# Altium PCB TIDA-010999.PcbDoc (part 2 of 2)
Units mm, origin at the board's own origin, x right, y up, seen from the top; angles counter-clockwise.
Board outline 95 x 90.17 mm, 4 copper layers (Top Layer 1, Top Layer, Bottom Layer, Bottom Layer 1), stack 1.926 mm thick; 90 components, 100 nets, 358 pads, 545 vias.
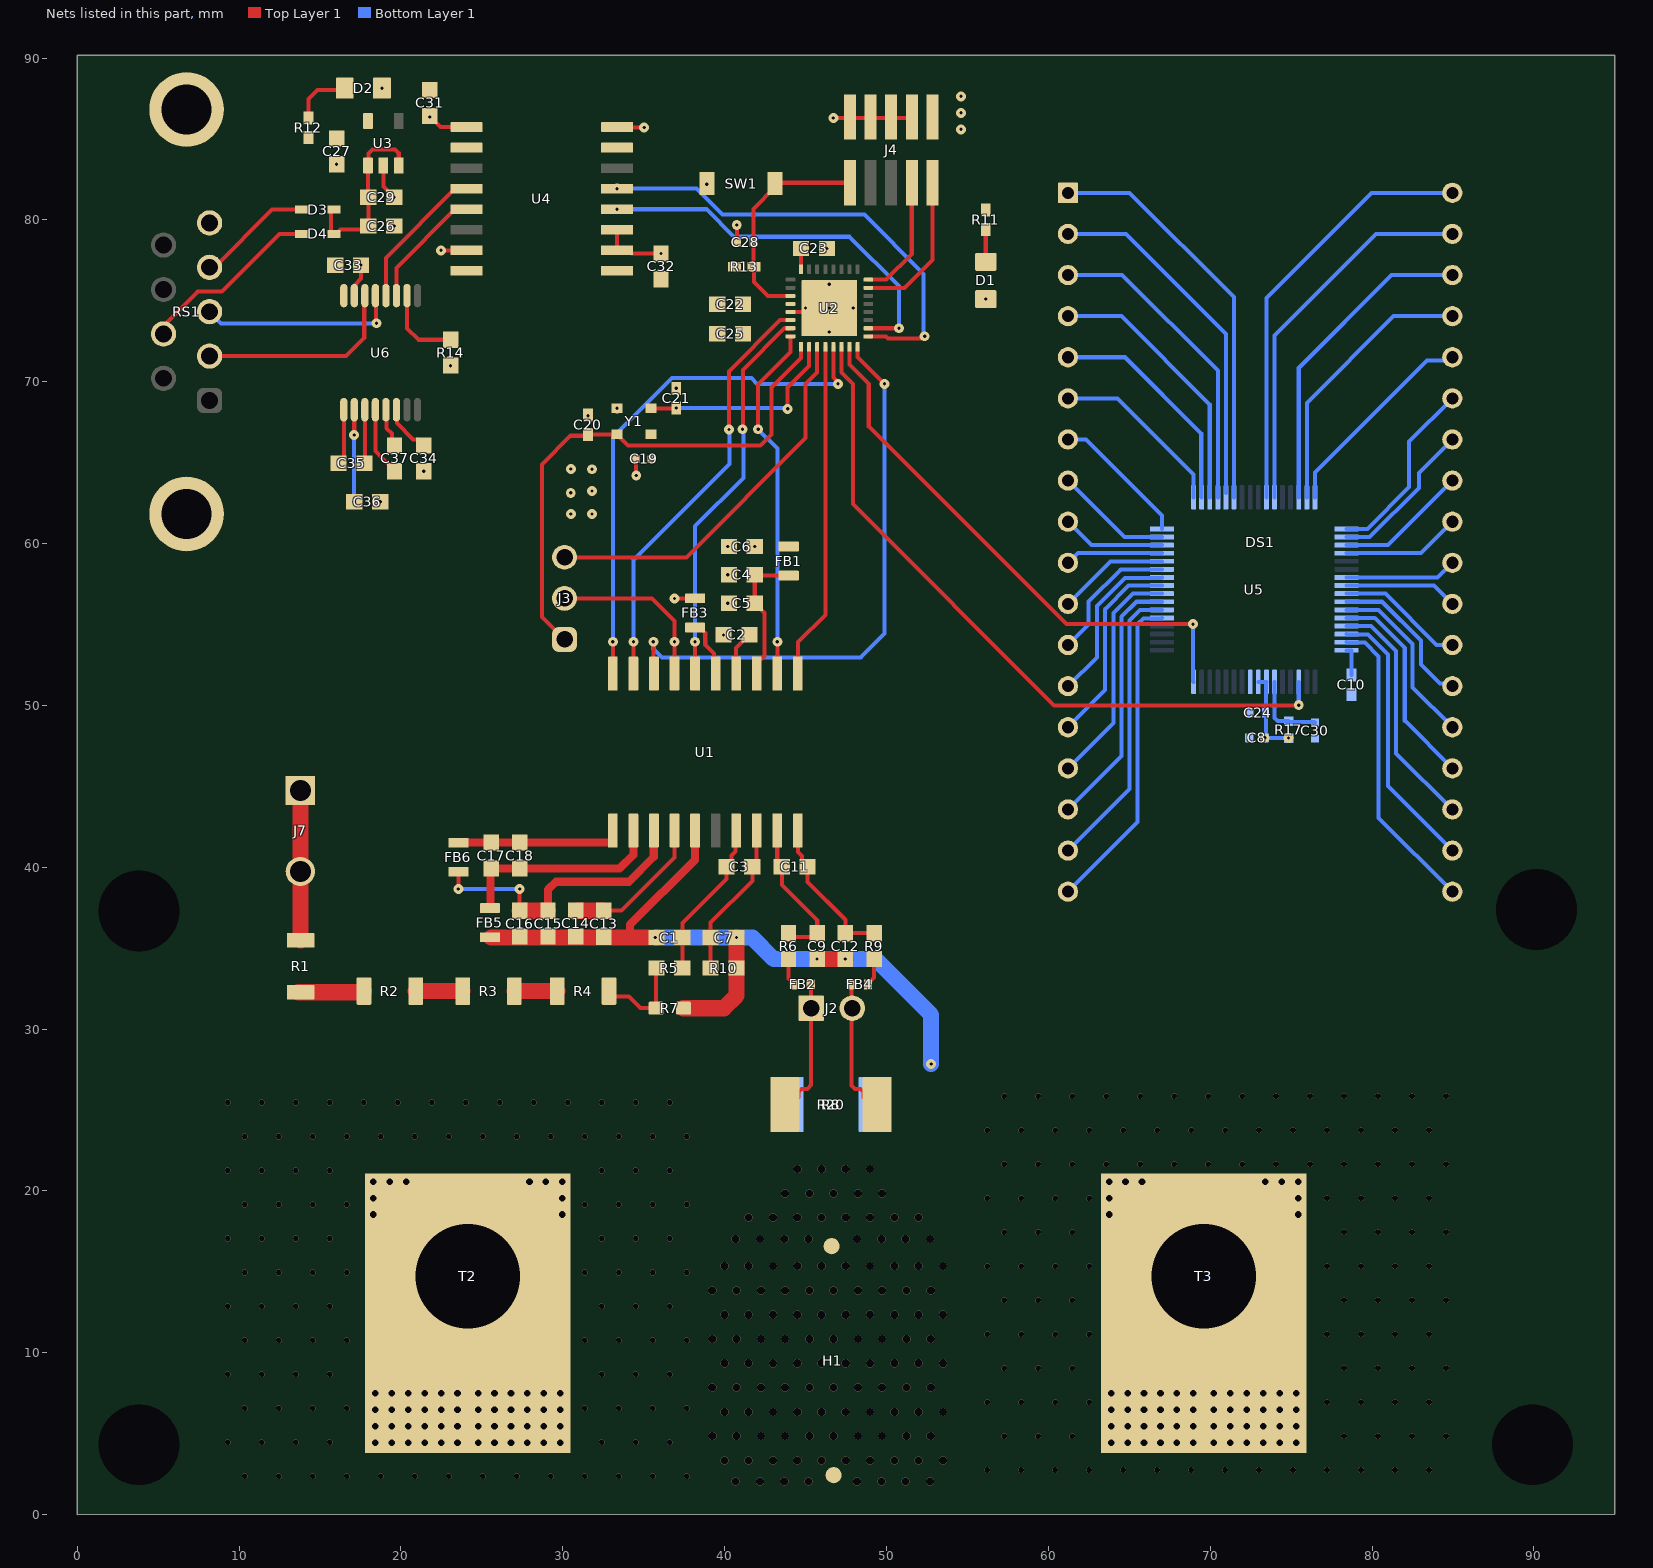
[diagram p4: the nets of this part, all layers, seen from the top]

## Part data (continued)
U4: library part CMP-0094636-1, Digikey Part Number=296-ISO6731DWRCT-ND, Manufacturer="Texas Instruments", Max Supply Voltage=5.5V, Min Supply Voltage=1.71V, Mouser Part Number=595-ISO6731DWR, Operating Temperature Range="-40°C to +125°C"
U5: library part CMP-0120470-1, "Automotive Mixed-Signal Microcontroller, LQFP64", Frequency_Fixed=32MHz, Manufacturer="Texas Instruments", Max Supply Voltage=3.6V, Min Supply Voltage=1.62V, Operating Temperature Range="-40°C to +125°C"
U6: library part CMP-0044119-1, "3-V to 5.5-V Multichannel RS-232 Line Driver / Receiver with ±15-kV IEC ESD Protection, -40 to 85 degC, 16-Pin SSOP (DB), Green (RoHS & no Sb/Br)", Drivers Per Package=2, Supply Voltage(s)(V)="3.3 or 5.0"
Y1: library part CMP-0094615-2, "Crystal replacement: Ultra-low Power LVCMOS Oscillator 4-pin, VSON 3.2 x 2.5 x 0.9mm", Frequency Stability=20ppm, Frequency_Fixed=50MHz, Load Capacitance=15pF, Manufacturer="Texas Instruments", Max Supply Current=4mA, Max Supply Voltage=3.465V, Min Supply Voltage=2.375V, Operating Temperature Range="to +135°C", Part Number=CDC6CE05000CDLE

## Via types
v1: diameter 0.35, hole 0.35, Top Layer 1 to Bottom Layer 1, 225 vias
v2: diameter 0.5, hole 0.5, Top Layer 1 to Bottom Layer 1, 123 vias
v3: diameter 0.813, hole 0.406, Top Layer 1 to Bottom Layer 1, 116 vias
v4: diameter 0.61, hole 0.203, Top Layer 1 to Bottom Layer 1, tented both sides, 76 vias
v5: diameter 0.5, hole 0.2, Top Layer 1 to Bottom Layer 1, 5 vias

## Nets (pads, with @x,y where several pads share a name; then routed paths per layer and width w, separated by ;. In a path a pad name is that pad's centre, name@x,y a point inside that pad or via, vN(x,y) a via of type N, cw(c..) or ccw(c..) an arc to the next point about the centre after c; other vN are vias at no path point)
ADC_C\S\: U1.19 U2.6 | length 26.3
  Top Layer 1 w0.25: U1.19@34.362,51.967 v4(34.362,53.937) ; v4(40.272,67.053) 40.264,67.06 40.264,70.643 43.426,73.805 U2.6@44.068,73.805
  Bottom Layer 1 w0.25: v4(34.362,53.937) 34.362,58.977 40.307,64.922 40.307,67.018 v4(40.272,67.053)
ADC_CLK_IN: J3.2 U1.17 | length 10.6
  Top Layer 1 w0.25: J3.2@30.105,56.612 35.499,56.612 36.902,55.21 v4(36.902,53.937) U1.17@36.902,51.967
ADC_D\R\D\Y\: U1.16 U2.7 | length 24
  Top Layer 1 w0.25: U1.16@38.172,51.967 v4(38.172,53.937) ; v4(41.105,67.06) 41.138,67.093 41.138,70.73 43.713,73.305 U2.7@44.068,73.305
  Bottom Layer 1 w0.25: v4(38.172,53.937) 38.172,61.07 41.153,64.051 41.153,67.012 v4(41.105,67.06)
ADC_DIN_MSP_DOUT: U1.20 U2.13 | length 32.6
  Top Layer 1 w0.25: U1.20@33.092,51.967 v4(33.092,53.937) ; U2.13@46.718,72.155 46.718,70.257 47.007,69.968 v4(47.007,69.87)
  Bottom Layer 1 w0.25: v4(33.092,53.937) 33.092,66.575 36.745,70.228 41.648,70.228 42.006,69.87 v4(47.007,69.87)
ADC_DOUT_MSP_DIN: U1.12 U2.8 | length 22.2
  Top Layer 1 w0.25: v4(42.07,67.06) 42.07,69.836 44.068,71.834 U2.8@44.068,72.805 ; U1.12@43.252,51.967 43.253,51.968 43.253,53.935 v4(43.255,53.937)
  Bottom Layer 1 w0.25: v4(42.07,67.06) 43.255,65.875 v4(43.255,53.937)
ADC_SYNC_RESET: U1.11 U2.12 | length 20.9
  Top Layer 1 w0.25: U1.11@44.522,51.967 44.522,53.905 46.218,55.601 U2.12@46.218,72.155
Bus_In: FB2.2 J2.1 R8.2 R20.2 T2.1 | length 8.7
  Top Layer 1 w0.254: R8.2@43.448,25.852 R8.2@44.486,25.852 ; R8.2@44.571,25.768 44.571,26.127 44.747,26.304 45.107,26.304 45.343,26.54 45.344,29.923 FB2.2@45.345,32.658 ; FB2.2@45.29,32.603 FB2.2@45.442,32.755
  other v1: 10.357,2.364 12.457,2.364 14.557,2.364 16.657,2.364 18.757,2.364 20.857,2.364 22.957,2.364 25.057,2.364 27.157,2.364 29.257,2.364 31.357,2.364 33.457,2.364 35.557,2.364 37.657,2.364 9.307,4.464 11.407,4.464 13.507,4.464 15.607,4.464 32.407,4.464 34.507,4.464 36.607,4.464 10.357,6.564 12.457,6.564 14.557,6.564 16.657,6.564 31.357,6.564 33.457,6.564 35.557,6.564 37.657,6.564 9.307,8.664 11.407,8.664 13.507,8.664 15.607,8.664 32.407,8.664 34.507,8.664 36.607,8.664 10.357,10.764 12.457,10.764 14.557,10.764 16.657,10.764 31.357,10.764 33.457,10.764 35.557,10.764 37.657,10.764 9.307,12.864 11.407,12.864 13.507,12.864 15.607,12.864 32.407,12.864 34.507,12.864 36.607,12.864 10.357,14.964 12.457,14.964 14.557,14.964 16.657,14.964 31.357,14.964 33.457,14.964 35.557,14.964 37.657,14.964 9.307,17.064 11.407,17.064 13.507,17.064 15.607,17.064 32.407,17.064 34.507,17.064 36.607,17.064 10.357,19.164 12.457,19.164 14.557,19.164 16.657,19.164 31.357,19.164 33.457,19.164 35.557,19.164 37.657,19.164 9.307,21.264 11.407,21.264 13.507,21.264 15.607,21.264 32.407,21.264 34.507,21.264 36.607,21.264 10.357,23.364 12.457,23.364 14.557,23.364 16.657,23.364 18.757,23.364 20.857,23.364 22.957,23.364 25.057,23.364 27.157,23.364 29.257,23.364 31.357,23.364 33.457,23.364 35.557,23.364 37.657,23.364 9.307,25.464 11.407,25.464 13.507,25.464 15.607,25.464 17.707,25.464 19.807,25.464 21.907,25.464 24.007,25.464 26.107,25.464 28.207,25.464 30.307,25.464 32.407,25.464 34.507,25.464 36.607,25.464
  other v3: 18.415,4.445 19.431,4.445 20.447,4.445 21.463,4.445 22.479,4.445 23.495,4.445 24.765,4.445 25.781,4.445 26.797,4.445 27.813,4.445 28.829,4.445 29.845,4.445 18.415,5.461 19.431,5.461 20.447,5.461 21.463,5.461 22.479,5.461 23.495,5.461 24.765,5.461 25.781,5.461 26.797,5.461 27.813,5.461 28.829,5.461 29.845,5.461 18.415,6.477 19.431,6.477 20.447,6.477 21.463,6.477 22.479,6.477 23.495,6.477 24.765,6.477 25.781,6.477 26.797,6.477 27.813,6.477 28.829,6.477 29.845,6.477 18.415,7.493 19.431,7.493 20.447,7.493 21.463,7.493 22.479,7.493 23.495,7.493 24.765,7.493 25.781,7.493 26.797,7.493 27.813,7.493 28.829,7.493 29.845,7.493 18.288,18.542 29.972,18.542 18.288,19.558 29.972,19.558 18.288,20.574 19.304,20.574 20.32,20.574 27.94,20.574 28.956,20.574 29.972,20.574
DCDC_HGND: C17.2 C18.1 FB5.1 U1.2 | length 13.1
  Top Layer 1 w0.5: FB5.1@25.495,37.477 25.534,37.516 25.534,39.88 C17.2@25.573,39.919 C18.1@27.335,39.919 33.512,39.919 34.362,40.769 U1.2@34.362,42.267
DCDC_OUT: C17.1 C18.2 FB6.1 U1.1 | length 10.3
  Top Layer 1 w0.5: FB6.1@23.547,41.515 23.552,41.519 C17.1@25.573,41.519 C18.2@27.335,41.519 33.042,41.519 33.092,41.569 U1.1@33.092,42.267
GND: C2.2 C4.2 C5.1 C6.1 C8.1 C10.1 C19.1 C20.2 C21.1 C22.1 C23.1 C24.1 C25.1 C28.1 C30.1 C32.2 D1.2 FB3.2 J4.3 J4.5 J4.7 J4.9 SW1.1 U2.5 U2.33 U4.2 U4.3 U4.8 U5.41 Y1.2 | length 15.1
  Top Layer 1 w0.25: U4.3@33.352,79.388 U4.2@33.352,78.118 34.052,78.118 34.243,77.927 v4(36.068,77.927) ; U4.8@33.352,85.738 33.369,85.721 35.01,85.721 v4(35.027,85.705) ; C19.1@34.49,65.226 34.516,65.201 34.516,64.237 v4(34.541,64.211) ; v4@36.902,56.612 FB3.2@38.171,56.612 ; v4(40.745,79.689) 40.758,79.676 40.758,78.625 C28.1@40.77,78.613 ; U2.5@44.068,74.305 44.868,74.305 44.993,74.43 v5(44.993,74.555) ; v4(46.718,86.298) 51.497,86.298 J4.3@51.562,86.363
  other v4: 39.932,54.356 40.184,56.31 36.902,56.611 40.184,58.082 40.184,59.817 31.554,67.903 33.35,68.353 37.006,69.598 39.538,72.969 39.538,74.791 56.134,75.105 46.328,78.232 38.892,82.193
  other v5: 46.468,73.08 46.468,74.555 47.943,74.555 46.468,76.03
GND_ISO_RS: C26.2 C27.2 C29.2 C31.2 C33.1 C34.1 C36.1 D2.2 R14.1 RS1.5 RS1.10 RS1.11 U3.2 U4.9 U4.15 U6.15 | length 8.4
  Top Layer 1 w0.25: U6.15@17.119,75.32 17.158,75.358 17.158,75.986 17.536,76.365 v4(17.536,77.206) ; U3.2@18.912,83.361 18.912,82.049 v4(19.556,81.405) C29.2@19.581,81.405 ; v4(21.784,86.353) 21.834,86.353 22.449,85.738 U4.9@24.052,85.738 ; v4(22.477,78.118) U4.15@24.052,78.118
  other v4: 18.718,62.576 21.403,64.466 23.065,70.995 19.581,79.621 16.022,83.436 18.822,88.138
H_GND: C1.2 C7.1 C9.2 C12.1 C13.2 C14.2 C15.2 C16.2 FB4.2 FB5.2 J2.2 R7.1 R8.1 R10.1 R20.1 T3.1 U1.5 | length 58.1
  Top Layer 1 w0.254: FB4.2@47.844,32.749 47.844,29.923 47.844,26.507 48.042,26.308 48.401,26.308 48.581,26.129 R8.1@48.581,25.77 ; R8.1@48.659,25.848 R8.1@49.795,25.848
  Top Layer 1 w0.5: 34.158,35.657 34.158,36.453 38.16,40.455 U1.5@38.16,42.255
  Top Layer 1 w1: FB5.2@25.577,35.657 29.085,35.657 34.158,35.657 v4(35.707,35.657) C1.2@35.782,35.657 ; R7.1@37.457,31.289 39.955,31.289 40.732,32.066 R10.1@40.732,33.771 v4(40.732,35.657) ; v4(45.71,34.324) v4(47.449,34.324)
  Bottom Layer 1 w1: v4(35.707,35.657) 41.713,35.657 43.045,34.324 v4(45.71,34.324) v4(47.449,34.324) 48.366,34.324 48.379,34.338 49.297,34.338 52.757,30.877 v4(52.757,27.841)
  other v1: 56.221,2.752 58.321,2.752 60.421,2.752 62.521,2.752 64.621,2.752 66.721,2.752 68.821,2.752 70.921,2.752 73.021,2.752 75.121,2.752 77.221,2.752 79.321,2.752 81.421,2.752 83.521,2.752 57.271,4.852 59.371,4.852 61.471,4.852 78.271,4.852 80.371,4.852 82.471,4.852 84.571,4.852 56.221,6.952 58.321,6.952 60.421,6.952 62.521,6.952 77.221,6.952 79.321,6.952 81.421,6.952 83.521,6.952 57.271,9.052 59.371,9.052 61.471,9.052 78.271,9.052 80.371,9.052 82.471,9.052 84.571,9.052 56.221,11.152 58.321,11.152 60.421,11.152 62.521,11.152 77.221,11.152 79.321,11.152 81.421,11.152 83.521,11.152 57.271,13.252 59.371,13.252 61.471,13.252 78.271,13.252 80.371,13.252 82.471,13.252 84.571,13.252 56.221,15.352 58.321,15.352 60.421,15.352 62.521,15.352 77.221,15.352 79.321,15.352 81.421,15.352 83.521,15.352 57.271,17.452 59.371,17.452 61.471,17.452 78.271,17.452 80.371,17.452 82.471,17.452 84.571,17.452 56.221,19.552 58.321,19.552 60.421,19.552 62.521,19.552 77.221,19.552 79.321,19.552 81.421,19.552 83.521,19.552 57.271,21.652 59.371,21.652 61.471,21.652 63.571,21.652 65.671,21.652 67.771,21.652 69.871,21.652 71.971,21.652 74.071,21.652 76.171,21.652 78.271,21.652 80.371,21.652 82.471,21.652 84.571,21.652 56.221,23.752 58.321,23.752 60.421,23.752 62.521,23.752 64.621,23.752 66.721,23.752 68.821,23.752 70.921,23.752 73.021,23.752 75.121,23.752 77.221,23.752 79.321,23.752 81.421,23.752 83.521,23.752 57.271,25.852 59.371,25.852 61.471,25.852 63.571,25.852 65.671,25.852 67.771,25.852 69.871,25.852 71.971,25.852 74.071,25.852 76.171,25.852 78.271,25.852 80.371,25.852 82.471,25.852 84.571,25.852
  other v3: 63.881,4.445 64.897,4.445 65.913,4.445 66.929,4.445 67.945,4.445 68.961,4.445 70.231,4.445 71.247,4.445 72.263,4.445 73.279,4.445 74.295,4.445 75.311,4.445 63.881,5.461 64.897,5.461 65.913,5.461 66.929,5.461 67.945,5.461 68.961,5.461 70.231,5.461 71.247,5.461 72.263,5.461 73.279,5.461 74.295,5.461 75.311,5.461 63.881,6.477 64.897,6.477 65.913,6.477 66.929,6.477 67.945,6.477 68.961,6.477 70.231,6.477 71.247,6.477 72.263,6.477 73.279,6.477 74.295,6.477 75.311,6.477 63.881,7.493 64.897,7.493 65.913,7.493 66.929,7.493 67.945,7.493 68.961,7.493 70.231,7.493 71.247,7.493 72.263,7.493 73.279,7.493 74.295,7.493 75.311,7.493 63.754,18.542 75.438,18.542 63.754,19.558 75.438,19.558 63.754,20.574 64.77,20.574 65.786,20.574 73.406,20.574 74.422,20.574 75.438,20.574
HEAT: H1.1 H1.2
  other v2: 40.682,2.036 42.182,2.036 43.682,2.036 45.182,2.036 48.182,2.036 49.682,2.036 51.182,2.036 52.682,2.036 39.984,3.351 41.484,3.351 42.984,3.351 44.484,3.351 45.984,3.351 47.484,3.351 48.984,3.351 50.484,3.351 51.984,3.351 53.484,3.351 39.234,4.851 40.734,4.851 42.234,4.851 43.734,4.851 45.234,4.851 46.734,4.851 48.234,4.851 49.734,4.851 51.234,4.851 52.734,4.851 39.984,6.351 41.484,6.351 42.984,6.351 44.484,6.351 45.984,6.351 47.484,6.351 48.984,6.351 50.484,6.351 51.984,6.351 53.484,6.351 39.234,7.851 40.734,7.851 42.234,7.851 43.734,7.851 45.234,7.851 46.734,7.851 48.234,7.851 49.734,7.851 51.234,7.851 52.734,7.851 39.984,9.351 41.484,9.351 42.984,9.351 44.484,9.351 45.984,9.351 47.484,9.351 48.984,9.351 50.484,9.351 51.984,9.351 53.484,9.351 39.234,10.851 40.734,10.851 42.234,10.851 43.734,10.851 45.234,10.851 46.734,10.851 48.234,10.851 49.734,10.851 51.234,10.851 52.734,10.851 39.984,12.351 41.484,12.351 42.984,12.351 44.484,12.351 45.984,12.351 47.484,12.351 48.984,12.351 50.484,12.351 51.984,12.351 53.484,12.351 39.234,13.851 40.734,13.851 42.234,13.851 43.734,13.851 45.234,13.851 46.734,13.851 48.234,13.851 49.734,13.851 51.234,13.851 52.734,13.851 39.984,15.351 41.484,15.351 42.984,15.351 44.484,15.351 45.984,15.351 47.484,15.351 48.984,15.351 50.484,15.351 51.984,15.351 53.484,15.351 40.682,17.036 42.182,17.036 43.682,17.036 45.182,17.036 48.182,17.036 49.682,17.036 51.182,17.036 52.682,17.036 41.484,18.351 42.984,18.351 44.484,18.351 45.984,18.351 47.484,18.351 48.984,18.351 50.484,18.351 51.984,18.351 43.734,19.851 45.234,19.851 46.734,19.851 48.234,19.851 49.734,19.851 44.484,21.351 45.984,21.351 47.484,21.351 48.984,21.351
HFXIN: C20.1 J3.1 U2.9 Y1.3 | length 33.1
  Top Layer 1 w0.25: J3.1@30.105,54.072 28.702,55.476 28.702,64.876 30.488,66.662 31.464,66.662 C20.1@31.554,66.753 Y1.3@33.35,66.753 34.037,66.066 42.2,66.066 42.884,66.749 42.884,69.643 44.718,71.477 U2.9@44.718,72.155
HFXOUT: C21.2 U2.10 Y1.1 | length 12.9
  Top Layer 1 w0.25: Y1.1@35.45,68.353 36.994,68.353 v4(37.013,68.372) ; v4(43.891,68.322) 43.891,69.645 45.218,70.972 U2.10@45.218,72.155
  Bottom Layer 1 w0.25: v4(37.013,68.372) 43.841,68.372 v4(43.891,68.322)
HLDO_IN: C15.1 C16.1 FB6.2 U1.3 | length 18.3
  Top Layer 1 w0.25: FB6.2@23.486,39.669 FB6.2@23.547,39.607 ; v4(23.547,38.654) FB6.2@23.547,39.607 ; FB6.2@23.547,39.715 FB6.2@23.547,39.607 ; C16.1@27.335,37.312 v4(27.335,38.654)
  Top Layer 1 w0.5: C15.1@29.085,37.312 29.085,38.62 29.571,39.105 34.081,39.105 35.62,40.645 U1.3@35.62,42.255
  Top Layer 1 w1: C16.1@27.335,37.312 C15.1@29.085,37.312
  Bottom Layer 1 w0.25: v4(23.547,38.654) v4(27.335,38.654)
HLDO_OUT: C13.1 C14.1 U1.4 | length 9.1
  Top Layer 1 w0.25: C13.1@32.534,37.309 32.559,37.334 33.624,37.334 36.902,40.612 U1.4@36.902,42.267
  Top Layer 1 w1: C14.1@30.835,37.312 32.53,37.312 C13.1@32.534,37.309
I_N: C11.2 C12.2 R9.2 U1.10 | length 9.6
  Top Layer 1 w0.254: U1.10@44.522,42.267 44.522,40.947 44.776,40.692 44.776,40.382 C11.2@45.124,40.034 45.124,39.096 47.463,36.756 47.463,35.938 R9.2@49.51,35.938
I_P: C9.1 C11.1 R6.2 U1.9 | length 9.4
  Top Layer 1 w0.254: U1.9@43.252,42.267 43.252,40.306 C11.1@43.524,40.034 ; C11.1@43.549,40.034 43.549,38.895 45.725,36.719 45.725,35.938 45.475,35.688 R6.2@43.795,35.688
"LCD SEG 1": DS1.1 U5.6 | length 25.3
  Bottom Layer 1 w0.25: DS1.1@61.213,81.672 65.023,81.672 71.473,75.222 U5.6@71.473,62.855
"LCD SEG 2": DS1.36 U5.10 | length 26.5
  Bottom Layer 1 w0.25: U5.10@73.473,62.855 73.473,75.179 79.966,81.672 DS1.36@84.963,81.672
"LCD SEG 3": DS1.2 U5.5 | length 22.1
  Bottom Layer 1 w0.25: DS1.2@61.213,79.132 64.79,79.132 70.973,72.949 U5.5@70.973,63.138
"LCD SEG 4": DS1.35 U5.11 | length 23.6
  Bottom Layer 1 w0.25: U5.11@73.973,62.855 73.973,72.86 80.245,79.132 DS1.35@84.963,79.132
"LCD SEG 5": DS1.3 U5.4 | length 19.5
  Bottom Layer 1 w0.25: DS1.3@61.213,76.592 64.56,76.592 70.473,70.679 U5.4@70.473,62.855
"LCD SEG 6": DS1.34 U5.14 | length 19.9
  Bottom Layer 1 w0.25: U5.14@75.473,62.855 75.473,70.858 81.207,76.592 DS1.34@84.963,76.592
"LCD SEG 7": DS1.4 U5.3 | length 16.8
  Bottom Layer 1 w0.25: DS1.4@61.213,74.052 64.511,74.052 69.973,68.59 U5.3@69.973,62.855
"LCD SEG 8": DS1.33 U5.15 | length 17
  Bottom Layer 1 w0.25: U5.15@75.973,62.855 75.973,68.69 81.334,74.052 DS1.33@84.963,74.052
"LCD SEG 9": DS1.5 U5.2 | length 14.1
  Bottom Layer 1 w0.25: DS1.5@61.213,71.512 64.735,71.512 69.448,66.799 69.448,62.88 U5.2@69.473,62.855
"LCD SEG 10": DS1.32 U5.16 | length 13
  Bottom Layer 1 w0.25: U5.16@76.473,62.855 76.473,64.386 83.408,71.321 84.772,71.321 DS1.32@84.963,71.512
"LCD SEG 11": DS1.6 U5.1 | length 11.1
  Bottom Layer 1 w0.25: DS1.6@61.213,68.972 64.273,68.972 68.973,64.272 U5.1@68.973,62.855
"LCD SEG 12": DS1.31 U5.17 | length 11.5
  Bottom Layer 1 w0.25: U5.17@78.423,60.905 79.72,60.905 82.296,63.481 82.296,66.305 DS1.31@84.963,68.972
"LCD SEG 13": DS1.7 U5.64 | length 8.6
  Bottom Layer 1 w0.25: DS1.7@61.213,66.432 62.329,66.432 67.023,61.738 U5.64@67.023,60.905
"LCD SEG 14": DS1.30 U5.18 | length 9.6
  Bottom Layer 1 w0.25: U5.18@78.423,60.405 79.856,60.405 82.896,63.445 82.896,64.365 DS1.30@84.963,66.432
"LCD SEG 15": DS1.8 U5.63 | length 7.2
  Bottom Layer 1 w0.25: DS1.8@61.216,63.889 64.7,60.405 U5.63@67.023,60.405
"LCD SEG 16": DS1.29 U5.19 | length 8.2
  Bottom Layer 1 w0.25: U5.19@78.423,59.905 80.976,59.905 DS1.29@84.946,63.875
"LCD SEG 17": DS1.9 U5.62 | length 6.4
  Bottom Layer 1 w0.25: DS1.9@61.213,61.352 62.66,59.905 U5.62@67.023,59.905
"LCD SEG 18": DS1.28 U5.20 | length 7.3
  Bottom Layer 1 w0.25: U5.20@78.423,59.405 83.016,59.405 DS1.28@84.963,61.352
"LCD SEG 19": DS1.10 U5.61 | length 6.1
  Bottom Layer 1 w0.25: DS1.10@61.213,58.812 61.234,58.812 61.827,59.405 U5.61@67.023,59.405
"LCD SEG 20": DS1.27 U5.23 | length 6.9
  Bottom Layer 1 w0.25: U5.23@78.423,57.905 84.056,57.905 DS1.27@84.963,58.812
"LCD SEG 21": DS1.11 U5.60 | length 6.9
  Bottom Layer 1 w0.25: DS1.11@61.213,56.272 63.846,58.905 U5.60@67.023,58.905
"LCD SEG 22": DS1.26 U5.24 | length 7
  Bottom Layer 1 w0.25: U5.24@78.423,57.405 83.83,57.405 DS1.26@84.963,56.272
"LCD SEG 23": DS1.12 U5.59 | length 8.6
  Bottom Layer 1 w0.25: DS1.12@61.213,53.732 62.483,55.001 62.483,56.412 64.476,58.405 U5.59@67.023,58.405
"LCD SEG 24": DS1.25 U5.25 | length 7.9
  Bottom Layer 1 w0.25: U5.25@78.423,56.905 80.821,56.905 83.994,53.732 DS1.25@84.963,53.732
"LCD SEG 25": DS1.13 U5.58 | length 10.5
  Bottom Layer 1 w0.25: DS1.13@61.213,51.192 62.996,52.975 62.996,56.151 64.725,57.88 66.998,57.88 U5.58@67.023,57.905
"LCD SEG 26": DS1.24 U5.26 | length 9.6
  Bottom Layer 1 w0.25: U5.26@78.423,56.405 80.623,56.405 83.016,54.012 83.016,52.522 84.197,51.34 84.815,51.34 DS1.24@84.963,51.192
"LCD SEG 27": DS1.14 U5.57 | length 12.4
  Bottom Layer 1 w0.25: DS1.14@61.213,48.652 63.5,50.939 63.5,55.941 64.964,57.405 U5.57@67.023,57.405
"LCD SEG 28": DS1.23 U5.27 | length 11.1
  Bottom Layer 1 w0.25: U5.27@78.423,55.905 80.396,55.905 82.513,53.788 82.513,51.102 DS1.23@84.963,48.652
"LCD SEG 29": DS1.15 U5.56 | length 14.2
  Bottom Layer 1 w0.25: DS1.15@61.213,46.112 64.021,48.92 64.021,55.696 65.23,56.905 U5.56@67.023,56.905
"LCD SEG 30": DS1.22 U5.28 | length 13
  Bottom Layer 1 w0.25: U5.28@78.423,55.405 80.169,55.405 82.023,53.551 82.023,49.052 DS1.22@84.963,46.112
"LCD SEG 31": DS1.16 U5.55 | length 16.2
  Bottom Layer 1 w0.25: DS1.16@61.213,43.572 64.511,46.87 64.511,55.478 65.438,56.405 U5.55@67.023,56.405
"LCD SEG 32": DS1.21 U5.29 | length 14.9
  Bottom Layer 1 w0.25: U5.29@78.423,54.905 79.943,54.905 81.494,53.353 81.494,47.04 DS1.21@84.963,43.572
"LCD SEG 33": DS1.17 U5.54 | length 18.1
  Bottom Layer 1 w0.25: DS1.17@61.213,41.032 65.008,44.827 65.008,55.247 65.666,55.905 U5.54@67.023,55.905
"LCD SEG 34": DS1.19 U5.31 | length 18.8
  Bottom Layer 1 w0.25: U5.31@78.423,53.905 78.448,53.88 79.555,53.88 80.406,53.029 80.406,43.048 DS1.19@84.963,38.492
"LCD SEG 35": DS1.18 U5.53 | length 20
  Bottom Layer 1 w0.25: DS1.18@61.213,38.492 65.522,42.801 65.522,55.02 65.882,55.38 66.998,55.38 U5.53@67.023,55.405
"LCD SEG 36": DS1.20 U5.30 | length 16.8
  Bottom Layer 1 w0.25: U5.30@78.423,54.405 78.448,54.38 79.741,54.38 80.976,53.145 80.976,45.019 DS1.20@84.963,41.032
M0_CLKOUT: J3.3 U2.11 | length 23.9
  Top Layer 1 w0.25: J3.3@30.106,59.152 37.647,59.152 45.007,66.512 45.007,69.87 45.718,70.581 U2.11@45.718,72.155
Meter_RX_PC_TX: RS1.3 U6.13 | length 12.3
  Top Layer 1 w0.25: U6.13@18.419,75.32 18.454,75.285 18.454,73.645 v4(18.488,73.611)
  Bottom Layer 1 w0.25: RS1.3@8.175,74.327 8.89,73.611 v4(18.488,73.611)
Meter_TX_PC_RX: RS1.2 U6.14 | length 12.7
  Top Layer 1 w0.25: RS1.2@8.175,71.583 16.613,71.583 17.731,72.702 17.731,75.281 U6.14@17.769,75.32
NetC2_1: C2.1 U1.14 | length 2.7
  Top Layer 1 w0.25: U1.14@40.712,51.967 40.712,53.561 41.507,54.356 C2.1@41.532,54.356
NetC4_1: C4.1 C5.2 FB1.1 U1.13 | length 8.8
  Top Layer 1 w0.25: C5.2@41.859,56.31 C4.1@41.859,58.082 41.92,58.021 FB1.1@43.962,58.021 ; C5.2@41.884,56.31 42.234,55.96 42.234,55.935 42.457,55.712 42.457,53.038 42.31,52.892 42.157,52.892 41.982,52.717 U1.13@41.982,51.967
NetC10_2: C10.2 U5.32 | length 1.8
  Bottom Layer 1 w0.25: U5.32@78.423,53.405 78.702,53.405 78.727,53.38 C10.2@78.727,51.872
NetC30_2: C30.2 R17.1 U5.38 | length 4.8
  Bottom Layer 1 w0.25: U5.38@73.973,51.455 73.973,49.226 74.176,49.023 R17.1@74.851,49.023 74.888,48.986 76.436,48.986 C30.2@76.473,48.948
NetC34_2: C34.2 U6.6 | length 3.1
  Top Layer 1 w0.25: U6.6@19.719,68.27 19.741,68.248 19.741,67.443 20.744,66.441 21.053,66.441 21.403,66.091 C34.2@21.403,66.066
NetC35_1: C35.1 U6.3 | length 3.3
  Top Layer 1 w0.25: C35.1@17.738,64.958 17.769,64.989 U6.3@17.769,68.27
NetC35_2: C35.2 U6.1 | length 3.4
  Top Layer 1 w0.25: C35.2@16.138,64.958 16.469,65.289 U6.1@16.469,68.27
NetC36_2: C36.2 U6.2 | length 5.7
  Top Layer 1 w0.25: v4(17.106,66.705) 17.112,66.711 17.112,68.263 U6.2@17.119,68.27
  Bottom Layer 1 w0.25: v4(17.106,66.705) 17.112,66.698 17.112,62.583 v4(17.118,62.576)
NetC37_1: C37.1 U6.5 | length 2.4
  Top Layer 1 w0.25: U6.5@19.069,68.27 19.108,68.231 19.108,67.124 19.437,66.794 19.437,66.231 C37.1@19.603,66.066
NetC37_2: C37.2 U6.4 | length 4.3
  Top Layer 1 w0.25: U6.4@18.419,68.27 18.419,65.711 18.836,65.294 19.253,64.878 19.253,64.816 C37.2@19.603,64.466
NetD1_1: D1.1 R11.1 | length 2
  Top Layer 1 w0.25: D1.1@56.134,77.405 R11.1@56.134,79.41
NetD2_1: D2.1 R12.1 | length 3.7
  Top Layer 1 w0.25: R12.1@14.281,86.29 14.281,87.469 14.85,88.038 16.422,88.038 D2.1@16.522,88.138
NetFB2_1: FB2.1 R6.1 | length 1.8
  Top Layer 1 w0.25: R6.1@43.948,34.324 43.948,33.128 44.145,32.93 44.195,32.93 44.32,32.805 FB2.1@44.32,32.755
NetFB3_1: FB3.1 U1.15 | length 3.6
  Top Layer 1 w0.25: FB3.1@38.172,54.812 38.497,54.812 38.672,54.637 38.672,54.608 38.802,54.478 38.802,53.747 39.336,53.212 39.336,52.072 U1.15@39.442,51.967
NetFB4_1: FB4.1 R9.1 | length 1.7
  Top Layer 1 w0.25: FB4.1@48.845,32.757 48.845,32.807 49.239,33.201 R9.1@49.239,34.324
NetJ1_1: 
NetJ1_2: 
NetJ7_1: J7.1 J7.2 R1.1 | length 9.3
  Top Layer 1 w1: J7.1@13.781,44.743 13.79,44.734 13.79,35.49 R1.1@13.799,35.48
NetR1_2: R1.2 R2.1 | length 4.1
  Top Layer 1 w1: R1.2@13.651,32.28 17.665,32.28 17.715,32.33 R2.1@17.715,32.351
NetR2_2: R2.2 R3.1 | length 2.9
  Top Layer 1 w1: R2.2@20.915,32.351 R3.1@23.811,32.351
NetR3_2: R3.2 R4.1 | length 2.6
  Top Layer 1 w1: R3.2@27.011,32.351 R4.1@29.653,32.351
NetR4_2: R4.2 R5.1 R7.2 | length 5.8
  Top Layer 1 w0.25: R4.2@32.853,32.351 33.178,32.026 34.076,32.026 34.812,31.289 R7.2@35.757,31.289 35.757,33.747 R5.1@35.782,33.771
NetR14_2: R14.2 U6.10 | length 5
  Top Layer 1 w0.25: U6.10@20.369,75.32 20.369,73.299 21.074,72.595 R14.2@23.065,72.595
nRST: C28.2 J4.10 R13.1 SW1.2 U2.3 | length 14
  Top Layer 1 w0.25: R13.1@41.807,77.105 41.807,76.161 42.663,75.305 U2.3@44.068,75.305 ; R13.1@41.87,77.141 41.77,77.141 C28.2@41.77,78.613 41.77,80.679 43.113,82.022 SW1.2@43.113,82.247 43.159,82.293 J4.10@47.752,82.293
RS232_PORT_DTR: D3.2 RS1.4 | length 7.2
  Top Layer 1 w0.25: RS1.4@8.175,77.07 8.47,77.07 12.042,80.641 D3.2@13.861,80.641
RS232_PORT_RTS: D4.2 RS1.7 | length 11.4
  Top Layer 1 w0.25: RS1.7@5.33,72.955 5.581,73.206 5.581,73.699 7.444,75.562 8.928,75.562 12.505,79.139 D4.2@13.861,79.139
Serial_RX: U2.17 U4.5 | length 28.6
  Top Layer 1 w0.25: U2.17@48.868,72.805 49.972,72.805 50.102,72.675 52.125,72.675 52.261,72.811 v4(52.358,72.811)
  Bottom Layer 1 w0.25: v4(33.352,81.928) 38.267,81.928 39.876,80.319 48.632,80.319 52.289,76.661 52.289,72.879 v4(52.358,72.811)
Serial_RX_ISO: U4.12 U6.12 | length 9.1
  Top Layer 1 w0.25: U6.12@19.069,75.32 19.069,77.645 23.352,81.928 U4.12@24.052,81.928
Serial_TX: U2.18 U4.4 | length 23.9
  Top Layer 1 w0.25: U2.18@48.868,73.305 v4(50.77,73.305)
  Bottom Layer 1 w0.25: v4(33.352,80.658) 38.886,80.658 40.587,78.957 47.725,78.957 50.77,75.912 v4(50.77,73.305)
Serial_TX_ISO: U4.13 U6.11 | length 7.5
  Top Layer 1 w0.25: U6.11@19.719,75.32 19.719,77.025 23.352,80.658 U4.13@24.052,80.658
SPI_CLK: U1.18 U2.16 | length 36
  Top Layer 1 w0.25: v4(35.593,53.937) 35.612,53.917 35.612,51.986 U1.18@35.632,51.967 ; U2.16@48.218,72.155 48.218,71.534 v4(49.882,69.87)
  Bottom Layer 1 w0.25: v4(35.593,53.937) 35.6,53.93 35.6,53.482 36.116,52.966 48.408,52.966 49.882,54.439 v4(49.882,69.87)
SWCLK: J4.4 U2.24 | length 7.8
  Top Layer 1 w0.25: U2.24@48.868,76.305 49.984,76.305 51.562,77.883 J4.4@51.562,82.293
SWDIO: J4.2 U2.23 | length 9.5
  Top Layer 1 w0.25: U2.23@48.868,75.805 51.122,75.805 52.832,77.514 J4.2@52.832,82.293
TPS709_IN: C26.1 C29.1 D3.1 D4.1 U3.1 U3.3 | length 11.4
  Top Layer 1 w0.25: D3.1@15.861,80.641 15.812,80.641 15.687,80.516 15.687,79.264 15.812,79.139 16.011,79.139 16.271,79.399 17.76,79.399 C26.1@17.981,79.621 C29.1@17.981,81.405 17.962,81.424 U3.1@17.962,83.361 17.98,83.379 17.98,84.09 18.239,84.349 19.64,84.349 19.862,84.126 U3.3@19.862,83.361
UART_RX: U2.15 U5.48 | length 34.1
  Top Layer 1 w0.25: U2.15@47.718,72.155 47.718,71.057 48.905,69.87 48.905,67.237 61.121,55.02 v4(68.944,55.02)
  Bottom Layer 1 w0.25: v4(68.944,55.02) 68.944,52.178 68.948,52.174 68.948,51.48 U5.48@68.973,51.455
UART_TX: U2.14 U5.35 | length 44.1
  Top Layer 1 w0.25: U2.14@47.218,72.155 47.218,70.584 47.932,69.87 47.932,62.44 60.365,50.007 75.466,50.007 v4(75.473,50.014)
  Bottom Layer 1 w0.25: v4(75.473,50.014) U5.35@75.473,51.455
V_DIV+: C1.1 C3.1 R5.2 U1.7 | length 9.9
  Top Layer 1 w0.25: R5.2@37.382,33.771 C1.1@37.382,35.657 37.382,36.561 40.107,39.286 C3.1@40.107,40.038 ; C3.1@40.076,40.007 40.417,40.349 40.417,40.733 40.673,40.988 40.673,42.227 U1.7@40.712,42.267
V_DIV-: C3.2 C7.2 R10.2 U1.8 | length 9.7
  Top Layer 1 w0.25: C7.2@39.132,35.657 39.132,36.583 41.707,39.158 C3.2@41.707,40.038 41.982,40.313 U1.8@41.982,42.267
  Top Layer 1 w0.254: R10.2@39.132,33.771 C7.2@39.132,35.657
VCC: C6.2 C19.2 C22.2 C25.2 C32.1 FB1.2 J4.1 R11.2 R13.2 U2.4 U4.1 U4.7 Y1.4
  other v4: 41.859,59.817 30.499,61.83 31.809,61.83 30.488,63.135 31.809,63.246 30.499,64.601 31.809,64.589 54.61,85.593 54.61,86.615 54.61,87.63
VCC_ISO_RS: C27.1 C31.1 C33.2 R12.2 U3.5 U4.10 U4.16 U6.16
VCORE: C23.2 U2.32 | length 1.3
  Top Layer 1 w0.25: U2.32@44.718,76.955 44.718,77.13 C23.2@44.718,78.232
VDD_3V3: C8.2 C24.2 R17.2 U5.39 U5.40 | length 5.5
  Bottom Layer 1 w0.25: U5.40@72.973,51.455 U5.39@73.473,51.455 73.448,51.43 73.448,48.076 v4(73.372,48) 73.386,47.986 74.837,47.986 R17.2@74.851,47.973
  other v4: 74.844,47.98
pads on no net: H2. H3. H4. H5. J4.6 J4.8 RS1.1 RS1.6 RS1.8 RS1.9 U1.6 U2.1 U2.2 U2.19 U2.20 U2.21 U2.22 U2.25 U2.26 U2.27 U2.28 U2.29 U2.30 U2.31 U3.4 U4.6 U4.11 U4.14 U5.7 U5.8 U5.9 U5.12 U5.13 U5.21 U5.22 U5.33 U5.34 U5.36 U5.37 U5.42 U5.43 U5.44 U5.45 U5.46 U5.47 U5.49 U5.50 U5.51 U5.52 U6.7 U6.8 U6.9
copper on no net:
  other v4: 71.932,45.725 73.252,45.725 74.6,45.755 71.352,46.498 72.453,46.498 74.01,46.498 75.238,46.498

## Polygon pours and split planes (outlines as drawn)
VCC on Top Layer 1 "TOP_LAYER_1_VCC_P004" (solid, remove dead copper, pour order 4): 94.756,87.999 94.756,45.327 93.716,44.287 59.541,44.287 58.434,45.394 58.434,48.296 54.734,51.996 29.339,51.996 28.111,53.224 28.111,57.607 28.111,65.887 33.348,71.124 33.348,87.696 35.175,89.523 93.232,89.523
VCC_ISO_RS on Top Layer 1 "TOP_LAYER_1_VCC_ISO_RS_P000" (solid, remove dead copper, pour order 0): 0.757,88.387 2.032,89.662 23.248,89.662 24.086,88.824 24.086,58.606 22.869,57.389 1.285,57.389 0.446,58.228
GND on Top Layer "TOP_LAYER_GND_P006" (solid, remove dead copper, pour order 6): 94.756,87.999 94.756,45.327 93.716,44.287 59.541,44.287 58.434,45.394 58.434,48.333 54.771,51.996 29.339,51.996 28.111,53.224 28.111,57.607 28.111,65.887 33.348,71.124 33.348,87.696 35.175,89.523 93.232,89.523
GND_ISO_RS on Top Layer "TOP_LAYER_GND_ISO_RS_P001" (solid, remove dead copper, pour order 1): 0.757,88.387 2.032,89.662 23.248,89.662 24.086,88.824 24.086,58.606 22.869,57.389 1.285,57.389 0.446,58.228
VCC on Bottom Layer "BOTTOM_LAYER_VCC_P007" (solid, remove dead copper, pour order 7): 94.756,87.999 94.756,45.327 93.716,44.287 59.541,44.287 58.434,45.394 58.434,48.354 54.792,51.996 29.339,51.996 28.111,53.224 28.111,57.607 28.111,65.887 33.348,71.124 33.348,87.696 35.175,89.523 93.232,89.523
GND_ISO_RS on Bottom Layer "BOTTOM_LAYER_GND_ISO_RS_P003" (solid, remove dead copper, pour order 3): 0.757,88.387 2.032,89.662 23.248,89.662 24.086,88.824 24.086,58.606 22.869,57.389 1.285,57.389 0.446,58.228
GND on Bottom Layer 1 "BOTTOM_LAYER_1_GND_P005" (solid, remove dead copper, pour order 5): 94.756,87.999 94.756,45.327 93.716,44.287 59.541,44.287 58.434,45.394 58.434,50.783 57.221,51.996 29.339,51.996 28.111,53.224 28.111,57.607 28.111,65.885 33.348,71.121 33.348,87.695 35.175,89.523 93.232,89.523
GND_ISO_RS on Bottom Layer 1 "BOTTOM_LAYER_1_GND_ISO_RS_P002" (solid, remove dead copper, pour order 2): 0.757,88.387 2.032,89.662 23.248,89.662 24.086,88.824 24.086,58.606 22.869,57.389 1.285,57.389 0.446,58.228

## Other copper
Top Layer 1:
  region net H_GND: 85.021,2.54 83.624,1.143 56.337,1.143 55.043,2.436 55.043,17.253 48.924,23.372 48.924,27.322 50.177,28.575 83.878,28.575 85.021,27.432
  region net Bus_In: 8.128,2.54 9.525,1.143 36.812,1.143 38.105,2.436 38.105,17.253 44.225,23.372 44.225,27.322 42.972,28.575 9.271,28.575 8.128,27.432
  region net HEAT: 38.772,2.432 39.935,1.27 53.287,1.27 54.277,2.26 54.277,16.779 47.843,23.213 47.843,25.749 47.052,26.54 46.072,26.54 45.272,25.74 45.272,23.177 38.772,16.678
Top Layer:
  region net H_GND: 85.021,2.54 83.624,1.143 56.337,1.143 55.043,2.436 55.043,17.253 48.924,23.372 48.924,27.322 50.177,28.575 83.852,28.575 85.021,27.406
  region net Bus_In: 8.128,2.54 9.525,1.143 36.812,1.143 38.105,2.436 38.105,17.253 44.225,23.372 44.225,27.322 42.972,28.575 9.296,28.575 8.128,27.406
  region net HEAT: 38.772,2.432 39.935,1.27 53.287,1.27 54.277,2.26 54.277,16.779 47.843,23.213 47.843,25.749 47.052,26.54 46.072,26.54 45.272,25.74 45.272,23.177 38.772,16.678
Bottom Layer:
  region net H_GND: 85.021,2.54 83.624,1.143 56.337,1.143 55.043,2.436 55.043,17.253 48.924,23.372 48.924,27.322 50.177,28.575 83.852,28.575 85.021,27.406
  region net Bus_In: 8.128,2.54 9.525,1.143 36.812,1.143 38.105,2.436 38.105,17.253 44.225,23.372 44.225,27.322 42.972,28.575 9.296,28.575 8.128,27.406
  region net HEAT: 38.772,2.432 39.935,1.27 53.287,1.27 54.277,2.26 54.277,16.779 47.843,23.213 47.843,25.749 47.052,26.54 46.072,26.54 45.272,25.74 45.272,23.177 38.772,16.678
Bottom Layer 1:
  region net H_GND: 85.021,2.54 83.624,1.143 56.337,1.143 55.043,2.436 55.043,17.253 48.924,23.372 48.924,27.322 50.177,28.575 83.878,28.575 85.021,27.432
  region net Bus_In: 8.128,2.54 9.525,1.143 36.812,1.143 38.105,2.436 38.105,17.253 44.225,23.372 44.225,27.322 42.972,28.575 9.271,28.575 8.128,27.432
  region net HEAT: 38.772,2.432 39.935,1.27 53.287,1.27 54.277,2.26 54.277,16.779 47.843,23.213 47.843,25.749 47.052,26.54 46.072,26.54 45.272,25.74 45.272,23.177 38.772,16.678

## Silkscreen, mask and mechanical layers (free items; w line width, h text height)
Top Overlay:
  text "TIDA-010999" at 62.103,30.099 h2.75
M1 Board Outline:
  the board outline again, w0.254
M9 Title Sheet:
  drawing of 57 lines, arcs and shapes, not listed
  text "1" at 18.792,204.254 h1.78
  text "2" at 82.182,204.254 h1.78
  text "3" at 145.411,204.254 h1.78
  text "4" at 209.08,204.254 h1.78
  text "5" at 272.555,204.254 h1.78
  text "6" at 336.182,204.254 h1.78
  text "A" at -10.579,175.222 h1.78
  text "A" at 365.341,175.222 h1.78
  text "B" at -10.579,114.77 h1.78
  text "B" at 365.341,114.77 h1.78
  text "C" at -10.579,54.445 h1.78
  text "C" at 365.341,54.445 h1.78
  text "PROJECT TITLE:" at 288.125,7.175 h1.14
  text ".PRJ_Title" at 289.395,3.789 h1.78
  text "DESIGNED FOR:" at 288.125,-0.47 h1.14
  text ".PRJ_Customer" at 289.395,-4.026 h1.78
  text "D" at -10.579,-5.753 h1.78
  text "D" at 365.341,-5.753 h1.78
  text "FILE NAME:" at 288.125,-8.09 h1.14
  text ".PCB_File_Name_No_Path" at 289.395,-11.138 h1.78
  text "Texas Instruments (TI) and/or its licensors do not warrant the accuracy or completeness of this specification" at 161.9,-15.249 h1.14
  text "ENGINEER:" at 288.125,-15.456 h1.14
  text "LAYOUT BY:" at 326.352,-15.456 h1.14
  text "or any information contained therein. TI and/or its licensors do not warrant that this design will meet" at 160.757,-18.111 h1.14
  text ".PRJ_Engineer" at 289.395,-19.393 h1.78
  text ".PCB_Layout" at 327.635,-19.393 h1.78
  text "the specifications, will be suitable for your application or fit for any particular purpose, or will operate in" at 160.757,-20.972 h1.14
  text "ALTIUM DESIGNER VERSION:" at 326.352,-23.33 h1.14
  text "an implementation. TI and/or its licensors do not warrant that the design is production worthy. You should" at 160.757,-23.834 h1.14
  text "completely validate and test your design implementation to confirm the system functionality for your application." at 161.9,-26.696 h1.14
  text ".print_Scale" at 289.395,-26.717 h1.78
  text ".Application_BuildNumber" at 327.635,-26.717 h1.78
  text "1" at 18.792,-31.966 h1.78
  text "2" at 82.182,-31.966 h1.78
  text "3" at 145.411,-31.966 h1.78
  text "4" at 209.08,-31.966 h1.78
  text "5" at 272.555,-31.966 h1.78
  text "6" at 336.182,-31.966 h1.78
M17 Embedded Cavity:
  text ".Layer_Name" at 14.656,-21.679 h1.52
M18 Embedded Assembly:
  text ".Layer_Name" at 14.656,-21.679 h1.52
M19 Embedded Keepout:
  text ".Layer_Name" at 14.656,-21.679 h1.52

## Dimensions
0,0.127 to 94.996,90.17 on M2 Board Dimensions
0,0.127 to 0,50.797 on M2 Board Dimensions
